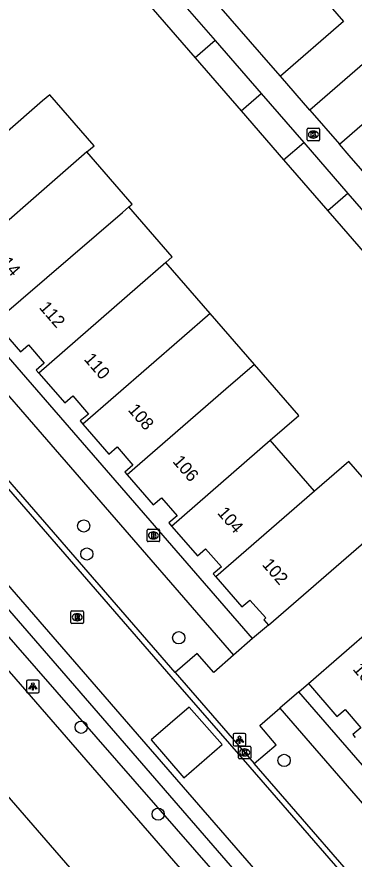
# Model space of a CAD drawing. Extents: x 155888 to 156864, y 383882 to 384671.
# Drawn here: x 156425.1 to 156452, y 384143.5 to 384210.8 of the extents above; entities that cross this region are included whole.
import ezdxf

# ---------------------------------------------------------------- set-up
doc = ezdxf.new("R2010")
doc.units = 0
for name, color, linetype in [('IMGEO_Boom', 7, 'Continuous'), ('IMGEO_Brandkraan', 7, 'Continuous'), ('IMGEO_Greppel_droge_sloot', 7, 'Continuous'), ('IMGEO_Kolk', 7, 'Continuous'), ('IMGEO_Lichtpunt', 7, 'Continuous'), ('IMGEO_OVBaan_gesloten', 7, 'Continuous'), ('IMGEO_Pand', 7, 'Continuous'), ('IMGEO_Pand_nummerreeks', 7, 'Continuous'), ('IMGEO_Rijbaan_lokaal_gesloten', 7, 'Continuous'), ('IMGEO_Rijbaan_lokaal_open', 7, 'Continuous'), ('IMGEO_Rioolput', 7, 'Continuous'), ('IMGEO_Voetpad_open', 7, 'Continuous')]:
    doc.layers.add(name, color=color, linetype=linetype)

msp = doc.modelspace()

# ---------------------------------------------------------------- linework, layer by layer
at = {"layer": 'IMGEO_Boom'}
for centre in [(156430.401, 384170.091), (156430.652, 384167.852), (156438.001, 384161.155), (156430.198, 384154.001), (156446.429, 384151.356), (156436.356, 384147.06)]:
    msp.add_circle(centre, 0.489, dxfattribs=at)
at = {"layer": 'IMGEO_Brandkraan'}
for p, q in [((156435.475, 384168.913), (156435.475, 384169.765)), ((156435.55, 384169.839), (156436.402, 384169.839)), ((156436.476, 384169.765), (156436.476, 384168.913)), ((156435.986, 384169.059), (156435.961, 384169.059)), ((156435.963, 384169.619), (156435.988, 384169.619)), ((156436.402, 384168.839), (156435.55, 384168.839))]:
    msp.add_line(p, q, dxfattribs=at)
for points in [[(156435.475, 384168.913), (156435.475, 384169.765)], [(156435.55, 384169.839), (156436.402, 384169.839)], [(156436.476, 384169.765), (156436.476, 384168.913)], [(156435.823, 384169.539), (156435.823, 384169.139), (156436.036, 384169.139)], [(156436.054, 384169.539), (156435.823, 384169.539)], [(156436.002, 384169.458), (156435.948, 384169.458), (156435.948, 384169.382)], [(156435.948, 384169.382), (156436.001, 384169.382)], [(156436.01, 384169.306), (156435.948, 384169.306), (156435.948, 384169.225)], [(156435.948, 384169.225), (156436.01, 384169.225)], [(156436.402, 384168.839), (156435.55, 384168.839)]]:
    msp.add_lwpolyline(points, dxfattribs=at)
for centre, radius, start, end in [((156435.552, 384169.763), 0.0765, 91.55205, 178.44795), ((156435.552, 384169.763), 0.0765, 91.55205, 178.44795), ((156436.4, 384169.763), 0.0765, 1.55205, 88.44795), ((156436.4, 384169.763), 0.0765, 1.55205, 88.44795), ((156436.003, 384169.42), 0.0379, 267.82845, 90.93552), ((156436.011, 384169.265), 0.0404, 269.87594, 90.50774), ((156436.042, 384169.39), 0.251, 268.66757, 293.53466), ((156436.058, 384169.394), 0.145, 59.4692, 91.53667), ((156436.083, 384169.441), 0.0922, 285.51372, 58.15012), ((156436.088, 384169.249), 0.105, 301.31148, 78.98903), ((156435.552, 384168.915), 0.0765, 181.55205, 268.44795), ((156435.552, 384168.915), 0.0765, 181.55205, 268.44795), ((156436.4, 384168.915), 0.0765, 271.55205, 358.44795), ((156436.4, 384168.915), 0.0765, 271.55205, 358.44795)]:
    msp.add_arc(centre, radius, start, end, dxfattribs=at)
for centre, major_axis, ratio, start_param, end_param in [((156435.962, 384169.339), (-0.387, 0.002), 0.722429, 4.712389, 7.853982), ((156435.987, 384169.339), (-0.39, 0.002), 0.717154, 1.570796, 4.712389)]:
    msp.add_ellipse(centre, major_axis=major_axis, ratio=ratio, start_param=start_param, end_param=end_param, dxfattribs=at)
at = {"layer": 'IMGEO_Greppel_droge_sloot'}
msp.add_lwpolyline([(156519.582, 384053.811), (156500, 384076.291), (156482.527, 384096.349), (156446.804, 384137.574), (156406.998, 384183.444), (156399.832, 384191.076), (156396.295, 384193.376), (156445.697, 384136.86), (156481.572, 384095.447), (156500, 384074.342), (156518.628, 384053.007)], dxfattribs=at)
at = {"layer": 'IMGEO_Kolk'}
for p, q in [((156448.271, 384200.956), (156448.271, 384201.808)), ((156448.346, 384201.882), (156449.198, 384201.882)), ((156448.759, 384201.662), (156448.784, 384201.662)), ((156449.272, 384201.808), (156449.272, 384200.956)), ((156449.198, 384200.882), (156448.346, 384200.882)), ((156448.782, 384201.102), (156448.757, 384201.102)), ((156442.777, 384151.565), (156442.777, 384152.417)), ((156442.852, 384152.491), (156443.704, 384152.491)), ((156443.265, 384152.271), (156443.29, 384152.271)), ((156443.778, 384152.417), (156443.778, 384151.565)), ((156443.704, 384151.491), (156442.852, 384151.491)), ((156443.288, 384151.711), (156443.263, 384151.711))]:
    msp.add_line(p, q, dxfattribs=at)
for points in [[(156448.271, 384200.956), (156448.271, 384201.808)], [(156448.346, 384201.882), (156449.198, 384201.882)], [(156448.592, 384201.582), (156448.715, 384201.582), (156448.715, 384201.431), (156448.845, 384201.582), (156449.009, 384201.582), (156448.863, 384201.431), (156449.016, 384201.182), (156448.864, 384201.182), (156448.779, 384201.346), (156448.715, 384201.279), (156448.715, 384201.182), (156448.592, 384201.182), (156448.592, 384201.582)], [(156449.272, 384201.808), (156449.272, 384200.956)], [(156449.198, 384200.882), (156448.346, 384200.882)], [(156442.777, 384151.565), (156442.777, 384152.417)], [(156442.852, 384152.491), (156443.704, 384152.491)], [(156443.098, 384152.191), (156443.221, 384152.191), (156443.221, 384152.04), (156443.351, 384152.191), (156443.515, 384152.191), (156443.369, 384152.04), (156443.522, 384151.791), (156443.37, 384151.791), (156443.285, 384151.955), (156443.221, 384151.888), (156443.221, 384151.791), (156443.098, 384151.791), (156443.098, 384152.191)], [(156443.778, 384152.417), (156443.778, 384151.565)], [(156443.704, 384151.491), (156442.852, 384151.491)]]:
    msp.add_lwpolyline(points, dxfattribs=at)
for centre, start, end in [((156448.348, 384201.806), 91.55205, 178.44795), ((156448.348, 384201.806), 91.55205, 178.44795), ((156449.196, 384201.806), 1.55205, 88.44795), ((156449.196, 384201.806), 1.55205, 88.44795), ((156448.348, 384200.958), 181.55205, 268.44795), ((156448.348, 384200.958), 181.55205, 268.44795), ((156449.196, 384200.958), 271.55205, 358.44795), ((156449.196, 384200.958), 271.55205, 358.44795), ((156442.854, 384152.415), 91.55205, 178.44795), ((156442.854, 384152.415), 91.55205, 178.44795), ((156443.702, 384152.415), 1.55205, 88.44795), ((156443.702, 384152.415), 1.55205, 88.44795), ((156442.854, 384151.567), 181.55205, 268.44795), ((156442.854, 384151.567), 181.55205, 268.44795), ((156443.702, 384151.567), 271.55205, 358.44795), ((156443.702, 384151.567), 271.55205, 358.44795)]:
    msp.add_arc(centre, 0.0765, start, end, dxfattribs=at)
for centre, major_axis, ratio, start_param, end_param in [((156448.758, 384201.382), (-0.387, 0.002), 0.722429, 4.712389, 7.853982), ((156448.783, 384201.382), (-0.39, 0.002), 0.717154, 1.570796, 4.712389), ((156443.264, 384151.991), (-0.387, 0.002), 0.722429, 4.712389, 7.853982), ((156443.289, 384151.991), (-0.39, 0.002), 0.717154, 1.570796, 4.712389)]:
    msp.add_ellipse(centre, major_axis=major_axis, ratio=ratio, start_param=start_param, end_param=end_param, dxfattribs=at)
at = {"layer": 'IMGEO_Lichtpunt'}
for p, q in [((156425.835, 384157.668), (156425.835, 384156.861)), ((156425.835, 384157.668), (156425.835, 384156.861)), ((156426.737, 384157.763), (156425.929, 384157.763)), ((156426.737, 384157.763), (156425.929, 384157.763)), ((156426.831, 384156.861), (156426.831, 384157.668)), ((156426.831, 384156.861), (156426.831, 384157.668)), ((156425.929, 384156.767), (156426.737, 384156.767)), ((156425.929, 384156.767), (156426.737, 384156.767)), ((156443.27, 384153.503), (156442.462, 384153.503)), ((156443.27, 384153.503), (156442.462, 384153.503)), ((156442.368, 384153.408), (156442.368, 384152.601)), ((156442.368, 384153.408), (156442.368, 384152.601)), ((156443.364, 384152.601), (156443.364, 384153.408)), ((156443.364, 384152.601), (156443.364, 384153.408)), ((156442.462, 384152.507), (156443.27, 384152.507)), ((156442.462, 384152.507), (156443.27, 384152.507))]:
    msp.add_line(p, q, dxfattribs=at)
for points in [[(156426.209, 384157.332), (156426.248, 384157.304), (156426.06, 384157.042), (156426.022, 384157.069), (156426.209, 384157.332)], [(156426.311, 384157.284), (156426.358, 384157.284), (156426.358, 384156.962), (156426.311, 384156.962), (156426.311, 384157.284)], [(156426.421, 384157.304), (156426.459, 384157.331), (156426.646, 384157.069), (156426.607, 384157.041), (156426.421, 384157.304)], [(156442.742, 384153.072), (156442.781, 384153.044), (156442.593, 384152.782), (156442.555, 384152.809), (156442.742, 384153.072)], [(156442.844, 384153.024), (156442.891, 384153.024), (156442.891, 384152.702), (156442.844, 384152.702), (156442.844, 384153.024)], [(156442.954, 384153.044), (156442.992, 384153.071), (156443.179, 384152.809), (156443.14, 384152.781), (156442.954, 384153.044)]]:
    msp.add_lwpolyline(points, dxfattribs=at)
for centre in [(156426.334, 384157.466), (156442.867, 384153.206)]:
    msp.add_circle(centre, 0.0994, dxfattribs=at)
for centre, start, end in [((156425.929, 384157.668), 90, 180), ((156425.929, 384157.668), 90, 180), ((156426.737, 384157.668), 0, 90), ((156426.737, 384157.668), 0, 90), ((156425.929, 384156.861), 180, 270), ((156425.929, 384156.861), 180, 270), ((156426.737, 384156.861), 270, 0), ((156426.737, 384156.861), 270, 360), ((156442.462, 384153.408), 90, 180), ((156442.462, 384153.408), 90, 180), ((156443.27, 384153.408), 0, 90), ((156443.27, 384153.408), 0, 90), ((156442.462, 384152.601), 180, 270), ((156442.462, 384152.601), 180, 270), ((156443.27, 384152.601), 270, 0), ((156443.27, 384152.601), 270, 360)]:
    msp.add_arc(centre, 0.0946, start, end, dxfattribs=at)
at = {"layer": 'IMGEO_OVBaan_gesloten'}
for points in [[(156517.145, 384051.764), (156500, 384071.498), (156389.213, 384199.015)], [(156407.083, 384168.169), (156407.746, 384167.396), (156407.842, 384167.479), (156410.66, 384164.227), (156441.975, 384128.147), (156500, 384061.368), (156513.218, 384046.155)]]:
    msp.add_lwpolyline(points, dxfattribs=at)
at = {"layer": 'IMGEO_Pand'}
for points in [[(156447.974, 384214.124), (156451.186, 384210.428), (156446.141, 384206.043)], [(156461.465, 384214.6), (156448.498, 384203.327)], [(156437.371, 384212.98), (156440.91, 384208.905)], [(156435.768, 384211.587), (156439.308, 384207.512)], [(156440.91, 384208.905), (156439.308, 384207.512)], [(156440.91, 384208.905), (156444.602, 384204.656)], [(156439.308, 384207.512), (156442.989, 384203.275)], [(156448.498, 384203.327), (156446.141, 384206.043)], [(156450.865, 384200.599), (156455.915, 384204.988), (156459.122, 384201.298)], [(156430.655, 384199.988), (156431.226, 384200.485), (156427.683, 384204.559), (156427.112, 384204.062), (156424.083, 384201.428)], [(156442.989, 384203.275), (156444.602, 384204.656)], [(156444.602, 384204.656), (156447.997, 384200.747)], [(156448.498, 384203.327), (156450.865, 384200.599)], [(156442.989, 384203.275), (156446.395, 384199.354)], [(156446.395, 384199.354), (156447.997, 384200.747)], [(156447.997, 384200.747), (156451.54, 384196.67)], [(156430.655, 384199.988), (156419.712, 384190.473)], [(156434.007, 384195.597), (156434.273, 384195.828), (156430.655, 384199.988)], [(156446.395, 384199.354), (156449.937, 384195.276)], [(156451.54, 384196.67), (156449.937, 384195.276)], [(156451.54, 384196.67), (156455.08, 384192.594)], [(156423.259, 384186.391), (156433.493, 384195.149), (156434.007, 384195.597)], [(156436.966, 384191.155), (156437.481, 384191.603), (156434.007, 384195.597)], [(156449.937, 384195.276), (156453.478, 384191.201)], [(156436.966, 384191.155), (156434.704, 384189.188), (156426.801, 384182.316)], [(156440.512, 384187.078), (156436.966, 384191.155)], [(156440.512, 384187.078), (156438.243, 384185.11), (156430.343, 384178.242)], [(156444.054, 384183.004), (156440.512, 384187.078)], [(156423.259, 384186.391), (156425.338, 384184.005), (156425.986, 384184.57), (156427.251, 384183.119), (156426.59, 384182.558), (156426.801, 384182.316)], [(156444.054, 384183.004), (156441.78, 384181.032), (156433.884, 384174.168)], [(156445.321, 384176.951), (156447.597, 384178.93), (156444.054, 384183.004)], [(156426.801, 384182.316), (156428.883, 384179.929), (156429.531, 384180.494), (156430.796, 384179.041), (156430.131, 384178.487), (156430.343, 384178.242)], [(156430.343, 384178.242), (156432.425, 384175.845), (156433.075, 384176.409), (156434.33, 384174.966), (156433.681, 384174.401), (156433.884, 384174.168)], [(156437.434, 384170.087), (156445.321, 384176.951)], [(156448.855, 384172.877), (156445.321, 384176.951)], [(156455.332, 384170.957), (156451.604, 384175.253), (156448.855, 384172.877)], [(156433.884, 384174.168), (156435.967, 384171.775), (156436.615, 384172.339), (156437.869, 384170.897), (156437.22, 384170.333), (156437.434, 384170.087)], [(156448.855, 384172.877), (156440.969, 384166.02)], [(156445.189, 384162.155), (156452.583, 384168.581), (156455.332, 384170.957)], [(156437.434, 384170.087), (156439.507, 384167.7), (156440.156, 384168.264), (156441.413, 384166.821), (156440.764, 384166.257), (156440.969, 384166.02)], [(156448.379, 384157.493), (156456.294, 384164.363), (156459.05, 384166.755)], [(156440.969, 384166.02), (156443.054, 384163.619), (156443.7, 384164.172), (156444.961, 384162.739), (156444.802, 384162.601), (156445.189, 384162.155)], [(156448.379, 384157.493), (156450.661, 384154.854), (156451.311, 384155.417), (156452.565, 384153.969), (156451.919, 384153.421), (156452.122, 384153.187)]]:
    msp.add_lwpolyline(points, dxfattribs=at)
at = {"layer": 'IMGEO_Rijbaan_lokaal_gesloten'}
for points in [[(156395.631, 384206.125), (156395.653, 384206.088), (156395.745, 384205.951), (156395.847, 384205.822), (156395.961, 384205.703), (156396.428, 384205.193), (156399.273, 384201.968), (156437.383, 384158.067), (156443.7, 384150.805), (156476.876, 384112.6), (156481.951, 384106.723), (156483.127, 384105.407), (156500, 384085.986), (156516.29, 384067.237), (156517.607, 384065.738), (156518.453, 384064.739), (156519.101, 384063.991), (156519.163, 384063.918), (156519.227, 384063.847), (156519.291, 384063.776)], [(156527.288, 384046.812), (156520.535, 384054.614), (156504.298, 384073.374), (156500, 384078.319), (156478.069, 384103.539), (156435.386, 384152.651), (156395.779, 384198.307), (156392.544, 384201.972)]]:
    msp.add_lwpolyline(points, dxfattribs=at)
at = {"layer": 'IMGEO_Rijbaan_lokaal_open'}
for points in [[(156437.73, 384158.369), (156399.619, 384202.271), (156396.759, 384205.513)], [(156437.73, 384158.369), (156444.047, 384151.107)], [(156438.423, 384149.957), (156441.478, 384152.616), (156438.839, 384155.617), (156435.799, 384152.992), (156438.423, 384149.957)], [(156477.224, 384112.901), (156444.047, 384151.107)]]:
    msp.add_lwpolyline(points, dxfattribs=at)
at = {"layer": 'IMGEO_Rioolput'}
for p, q in [((156429.383, 384162.37), (156429.383, 384163.222)), ((156429.458, 384163.296), (156430.31, 384163.296)), ((156429.871, 384163.076), (156429.896, 384163.076)), ((156430.384, 384163.222), (156430.384, 384162.37)), ((156430.31, 384162.296), (156429.458, 384162.296)), ((156429.894, 384162.516), (156429.869, 384162.516))]:
    msp.add_line(p, q, dxfattribs=at)
for points in [[(156429.383, 384162.37), (156429.383, 384163.222)], [(156429.458, 384163.296), (156430.31, 384163.296)], [(156429.972, 384162.994), (156429.72, 384162.996), (156429.72, 384162.596)], [(156430.384, 384163.222), (156430.384, 384162.37)], [(156430.31, 384162.296), (156429.458, 384162.296)], [(156429.72, 384162.596), (156429.844, 384162.596), (156429.844, 384162.758), (156429.855, 384162.758)], [(156429.898, 384162.915), (156429.844, 384162.915), (156429.844, 384162.834)], [(156429.844, 384162.834), (156429.896, 384162.834)], [(156429.902, 384162.729), (156429.973, 384162.596), (156430.113, 384162.596), (156430.048, 384162.722)]]:
    msp.add_lwpolyline(points, dxfattribs=at)
for centre, radius, start, end in [((156429.46, 384163.22), 0.0765, 91.55205, 178.44795), ((156429.46, 384163.22), 0.0765, 91.55205, 178.44795), ((156429.971, 384162.884), 0.109, 350.36119, 89.41601), ((156430.308, 384163.22), 0.0765, 1.55205, 88.44795), ((156430.308, 384163.22), 0.0765, 1.55205, 88.44795), ((156429.46, 384162.372), 0.0765, 181.55205, 268.44795), ((156429.46, 384162.372), 0.0765, 181.55205, 268.44795), ((156429.854, 384162.705), 0.0533, 26.02933, 88.69889), ((156429.88, 384163.023), 0.19, 274.7715, 282.96867), ((156429.904, 384162.819), 0.0964, 77.00612, 93.18647), ((156429.918, 384162.876), 0.0378, 276.66336, 79.67722), ((156429.969, 384162.884), 0.112, 277.58423, 350.98172), ((156429.953, 384162.669), 0.108, 29.51342, 73.79051), ((156430.308, 384162.372), 0.0765, 271.55205, 358.44795), ((156430.308, 384162.372), 0.0765, 271.55205, 358.44795)]:
    msp.add_arc(centre, radius, start, end, dxfattribs=at)
for centre, major_axis, ratio, start_param, end_param in [((156429.87, 384162.796), (-0.387, 0.002), 0.722429, 4.712389, 7.853982), ((156429.895, 384162.796), (-0.39, 0.002), 0.717154, 1.570796, 4.712389)]:
    msp.add_ellipse(centre, major_axis=major_axis, ratio=ratio, start_param=start_param, end_param=end_param, dxfattribs=at)
at = {"layer": 'IMGEO_Voetpad_open'}
for points in [[(156446.141, 384206.043), (156445.38, 384206.914), (156440.486, 384212.547), (156439.717, 384213.427)], [(156443.915, 384161.094), (156408.135, 384202.27)], [(156457.297, 384193.205), (156456.534, 384194.093), (156451.631, 384199.716), (156450.865, 384200.599)], [(156419.063, 384186.621), (156442.384, 384159.766)], [(156445.189, 384162.155), (156443.915, 384161.094)], [(156443.915, 384161.094), (156442.384, 384159.766)], [(156442.384, 384159.766), (156440.805, 384158.384), (156439.47, 384159.889), (156437.73, 384158.369)], [(156447.623, 384156.834), (156448.379, 384157.493)], [(156447.623, 384156.834), (156446.092, 384155.517)], [(156483.427, 384115.614), (156447.623, 384156.834)], [(156444.047, 384151.107), (156445.796, 384152.598), (156444.501, 384154.132), (156446.092, 384155.517)], [(156446.092, 384155.517), (156481.885, 384114.292)]]:
    msp.add_lwpolyline(points, dxfattribs=at)

# ---------------------------------------------------------------- texts
at = {"layer": 'IMGEO_Pand_nummerreeks'}
for s, rotation, p in [('114', 310.95481, (156423.214, 384191.645)), ('112', 310.95481, (156426.789, 384187.526)), ('110', 310.95481, (156430.371, 384183.399)), ('108', 310.95599, (156433.89, 384179.344)), ('106', 310.95599, (156437.466, 384175.225)), ('104', 310.95599, (156441.043, 384171.103)), ('102', 310.95599, (156444.619, 384166.983)), ('100', 311.01211, (156451.877, 384158.617))]:
    msp.add_text(s, height=1, rotation=rotation, dxfattribs=at).set_placement(p)

doc.saveas('drawing.dxf')
